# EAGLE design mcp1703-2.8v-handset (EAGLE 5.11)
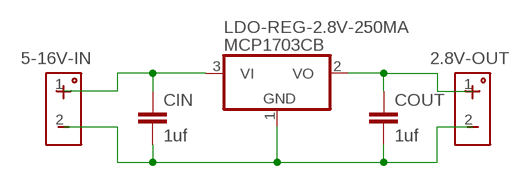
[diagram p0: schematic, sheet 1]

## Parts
2.8V-OUT  HEADER-POWER  [HEADER-POWER]
5-16V-IN  HEADER-POWER  [HEADER-POWER]
CIN  1uf  C-EUC0805  [C0805]
COUT  1uf  C-EUC0805  [C0805]
LDO-REG-2.8V-250MA  MCP1703CB  [SOT23]

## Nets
GND: 2.8V-OUT.2 5-16V-IN.2 CIN.2 COUT.2 LDO-REG-2.8V-250MA.1(GND)
N$2: 2.8V-OUT.1 COUT.1 LDO-REG-2.8V-250MA.2(VO)
N$3: 5-16V-IN.1 CIN.1 LDO-REG-2.8V-250MA.3(VI)

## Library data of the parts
2.8V-OUT 5-16V-IN = trl:HEADER-POWER
CIN COUT = rcl:C-EU: CAPACITOR, European symbol
LDO-REG-2.8V-250MA = linear:MCP1703: 250 mA, 16V, Low Quiescent Current LDO Regulator Source: http://ww1.microchip.com/downloads/en/DeviceDoc/22049b.pdf

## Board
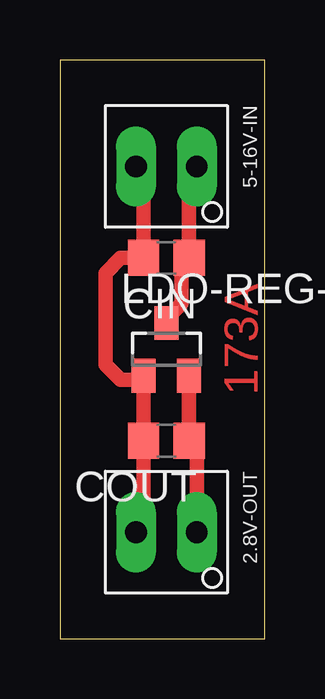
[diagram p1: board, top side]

Size 8.56 x 24.12 mm. Coordinates in mm from the lower left corner, seen from the top.
Outline: 0,0 8.56,0 8.56,24.12 0,24.12 0,0
Copper layers (1*16): Top 0.035mm / dielectric 1.5mm / Bottom 0.035mm
Design rules "default": minimum track width 10mil, minimum drill 0.6mm, track to track 8mil, track to pad 8mil, pad to pad 8mil, via to via 8mil, smd to smd 8mil, copper to edge 40mil, drill to drill 8mil, minimum pad ring 10mil, minimum via ring 8mil, stop-mask expansion 4mil, vias tented up to drill 0mil, thermal gap 10mil

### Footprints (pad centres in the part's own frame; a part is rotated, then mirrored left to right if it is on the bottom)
HEADER-POWER = drill 0.9 pad 1.676 long: 1 0,1.27; 2 0,-1.27
C0805 = smd 1.3 x 1.5: 1 -0.95,0; 2 0.95,0
SOT23 = smd 1 x 1.4: 1 -0.95,-1.1; 2 0.95,-1.1; 3 0,1.1

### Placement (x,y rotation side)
2.8V-OUT  4.45,4.45 270 top
5-16V-IN  4.45,19.68 270 top
CIN  4.45,15.88 180 top
COUT  4.45,8.26 180 top
LDO-REG-2.8V-250MA  4.45,12.06 0 top

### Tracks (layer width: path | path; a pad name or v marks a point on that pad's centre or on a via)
GND
  Top 0.61: 2.8V-OUT.2 3.5,4.45 COUT.2 LDO-REG-2.8V-250MA.1 3.33,10.79 2.54,10.79 1.91,11.43 1.91,15.24 2.54,15.88 CIN.2 3.5,19.36 5-16V-IN.2
N$2
  Top 0.61: LDO-REG-2.8V-250MA.2 COUT.1 5.71,8.26 2.8V-OUT.1
N$3
  Top 0.61: LDO-REG-2.8V-250MA.3 4.45,13.34 5.08,13.97 5.08,15.56 CIN.1 5.39,19.36 5-16V-IN.1

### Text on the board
Top: 173A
